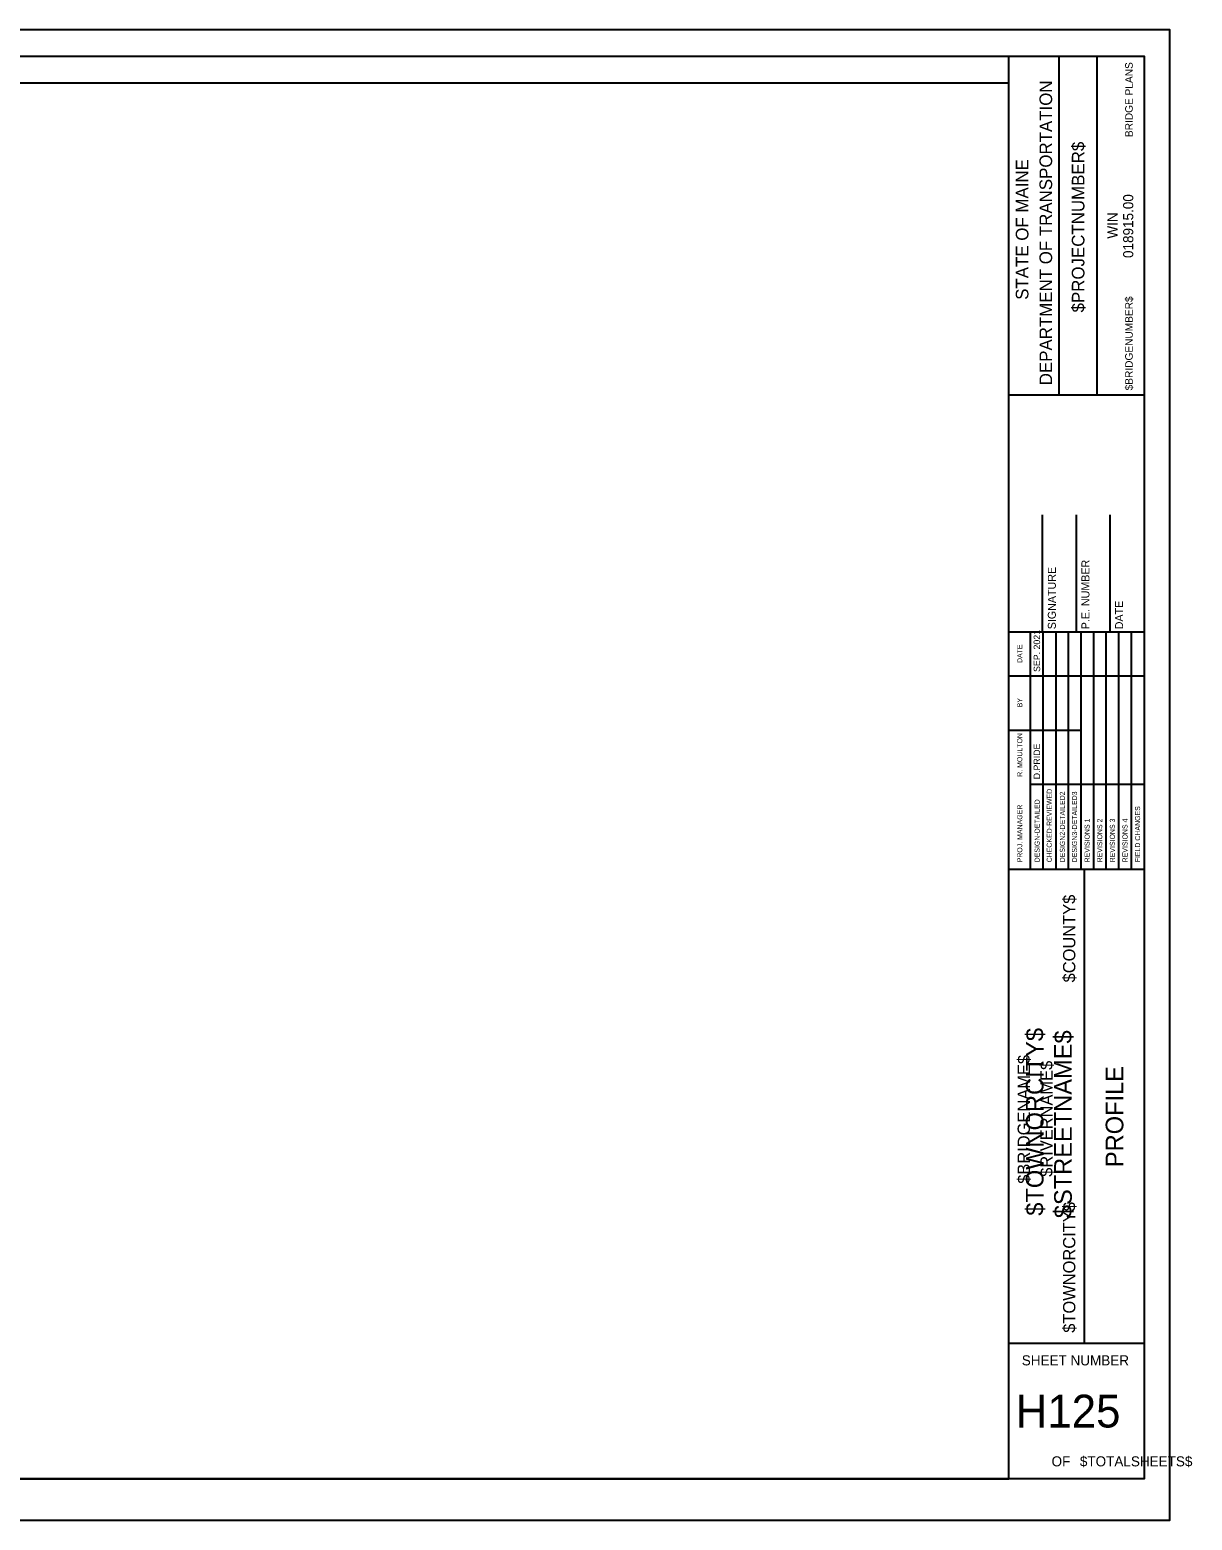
# Model space of a CAD drawing. Extents: x 9960 to 10818, y 9985 to 10535.
# Drawn here: x 10389 to 10818, y 9985 to 10535 of the extents above; entities that cross this region are included whole.
import ezdxf

# ---------------------------------------------------------------- set-up
doc = ezdxf.new("R2010")
doc.units = 0
for name, color, linetype in [('BORDER', 7, 'Continuous'), ('BRIDGE_TITLE', 7, 'Continuous'), ('CLIPS', 7, 'Continuous'), ('HIGHWAY_TITLE', 7, 'Continuous'), ('PLOT BOUNDARY', 7, 'Continuous')]:
    doc.layers.add(name, color=color, linetype=linetype)

msp = doc.modelspace()

# ---------------------------------------------------------------- linework, layer by layer
at = {"layer": 'BORDER'}
for p, q in [((10750, 10000), (10750, 10525)), ((10768.64, 10399.99), (10768.64, 10524.99)), ((10782.62, 10399.99), (10782.62, 10524.99)), ((10750, 10399.97), (10800, 10399.97)), ((10762.5, 10312.51), (10762.5, 10355.75)), ((10775, 10312.51), (10775, 10355.75)), ((10787.5, 10312.51), (10787.5, 10355.75)), ((10750, 10312.51), (10800, 10312.51)), ((10750, 10225.01), (10800, 10225.01)), ((10777.96, 10050.01), (10777.96, 10225.01)), ((10750, 10050.01), (10800, 10050.01))]:
    msp.add_line(p, q, dxfattribs=at)
msp.add_lwpolyline([(10000, 10525), (10800, 10525), (10800, 10000), (10000, 10000)], close=True, dxfattribs=at)
for points in [[(10758.07, 10296.26), (10758.07, 10312.51)], [(10762.74, 10225.03), (10762.74, 10312.51)], [(10767.4, 10312.51), (10767.4, 10225.03)], [(10772.05, 10225.03), (10772.05, 10312.51)], [(10776.71, 10225.03), (10776.71, 10312.51)], [(10781.37, 10225.03), (10781.37, 10312.51)], [(10786.03, 10225.03), (10786.03, 10312.51)], [(10790.69, 10225.03), (10790.69, 10312.51)], [(10795.35, 10225.03), (10795.35, 10312.51)], [(10758.08, 10225.03), (10758.08, 10308.98)], [(10750, 10296.26), (10800, 10296.26)], [(10750, 10276.26), (10758.08, 10276.26)], [(10758.07, 10276.26), (10776.71, 10276.26)], [(10758.07, 10256.26), (10800, 10256.26)]]:
    msp.add_lwpolyline(points, dxfattribs=at)
at = {"layer": 'CLIPS'}
msp.add_lwpolyline([(10000, 10000), (10750, 10000), (10750, 10515), (10000, 10515)], close=True, dxfattribs=at)
at = {"layer": 'PLOT BOUNDARY'}
msp.add_lwpolyline([(9959.53, 9984.7), (10809.53, 9984.7), (10809.53, 10534.7), (9959.53, 10534.7)], close=True, dxfattribs=at)

# ---------------------------------------------------------------- texts
at = {"layer": 'BORDER'}
for s, height, rotation, p in [('DEPARTMENT OF TRANSPORTATION', 4.6588, 90, (10766.03, 10403.53)), ('$PROJECTNUMBER$', 4.6588, 90, (10777.96, 10430.4)), ('STATE OF MAINE', 4.6588, 90, (10757.28, 10435.06)), ('018915.00', 3.726, 90, (10795.98, 10450.49)), ('WIN', 3.726, 90, (10790.18, 10457.65)), ('SIGNATURE', 2.953, 90, (10767.4, 10313.48)), ('P.E. NUMBER', 2.9528, 90, (10779.8, 10313.48)), ('DATE', 2.953, 90, (10792.21, 10313.48)), ('SEP. 2021', 2.423, 90, (10761.61, 10297.74)), ('DATE', 1.857, 90, (10755.02, 10301.04)), ('BY', 1.857, 90, (10755.02, 10284.69)), ('R. MOULTON', 1.864, 90, (10755.02, 10259.03)), ('D.PRIDE', 2.423, 90, (10761.61, 10258.13)), ('CHECKED-REVIEWED', 1.8637, 90, (10765.91, 10227.46)), ('DESIGN2-DETAILED2', 1.8637, 90, (10770.75, 10227.46)), ('DESIGN3-DETAILED3', 1.8637, 90, (10775.22, 10227.46)), ('PROJ. MANAGER', 1.8637, 90, (10755.02, 10227.46)), ('DESIGN-DETAILED', 1.8637, 90, (10761.43, 10227.46)), ('FIELD CHANGES', 1.8637, 90, (10798.51, 10227.46)), ('REVISIONS 1', 1.8637, 90, (10779.88, 10227.46)), ('REVISIONS 2', 1.8637, 90, (10784.54, 10227.46)), ('REVISIONS 3', 1.8637, 90, (10789.2, 10227.46)), ('REVISIONS 4', 1.8637, 90, (10793.86, 10227.46)), ('PROFILE', 6.521, 90, (10792.32, 10115)), ('SHEET NUMBER', 3.7264, 360, (10754.83, 10041.83)), ('H125', 12.097, 360, (10752.58, 10018.91)), ('OF', 3.726, 360, (10765.83, 10004.56)), ('$TOTALSHEETS$', 3.7264, 360, (10776.28, 10004.56))]:
    msp.add_text(s, height=height, rotation=rotation, dxfattribs=at).set_placement(p)
at = {"layer": 'BRIDGE_TITLE'}
for s, height, p in [('BRIDGE PLANS', 2.795, (10795.79, 10495.12)), ('$BRIDGENUMBER$', 2.795, (10795.79, 10401.65)), ('$COUNTY$', 4.536, (10774.6, 10183.17)), ('$BRIDGENAME$', 4.5358, (10757.83, 10108.86)), ('$RIVERNAME$', 4.5358, (10766.22, 10111.43)), ('$TOWNORCITY$', 4.5358, (10774.6, 10053.88))]:
    msp.add_text(s, height=height, rotation=90, dxfattribs=at).set_placement(p)
at = {"layer": 'HIGHWAY_TITLE'}
for s, p in [('$TOWNORCITY$', (10762.86, 10097.06)), ('$STREETNAME$', (10773.3, 10096.16))]:
    msp.add_text(s, height=6.5214, rotation=90, dxfattribs=at).set_placement(p)

doc.saveas('drawing.dxf')
